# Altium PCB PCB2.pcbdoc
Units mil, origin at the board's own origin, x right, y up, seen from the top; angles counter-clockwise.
Board outline 3315 x 2785 mil, 2 copper layers (Top Layer, Bottom Layer), stack 62.206 mil thick; 34 components, 22 nets, 101 pads, 38 vias.
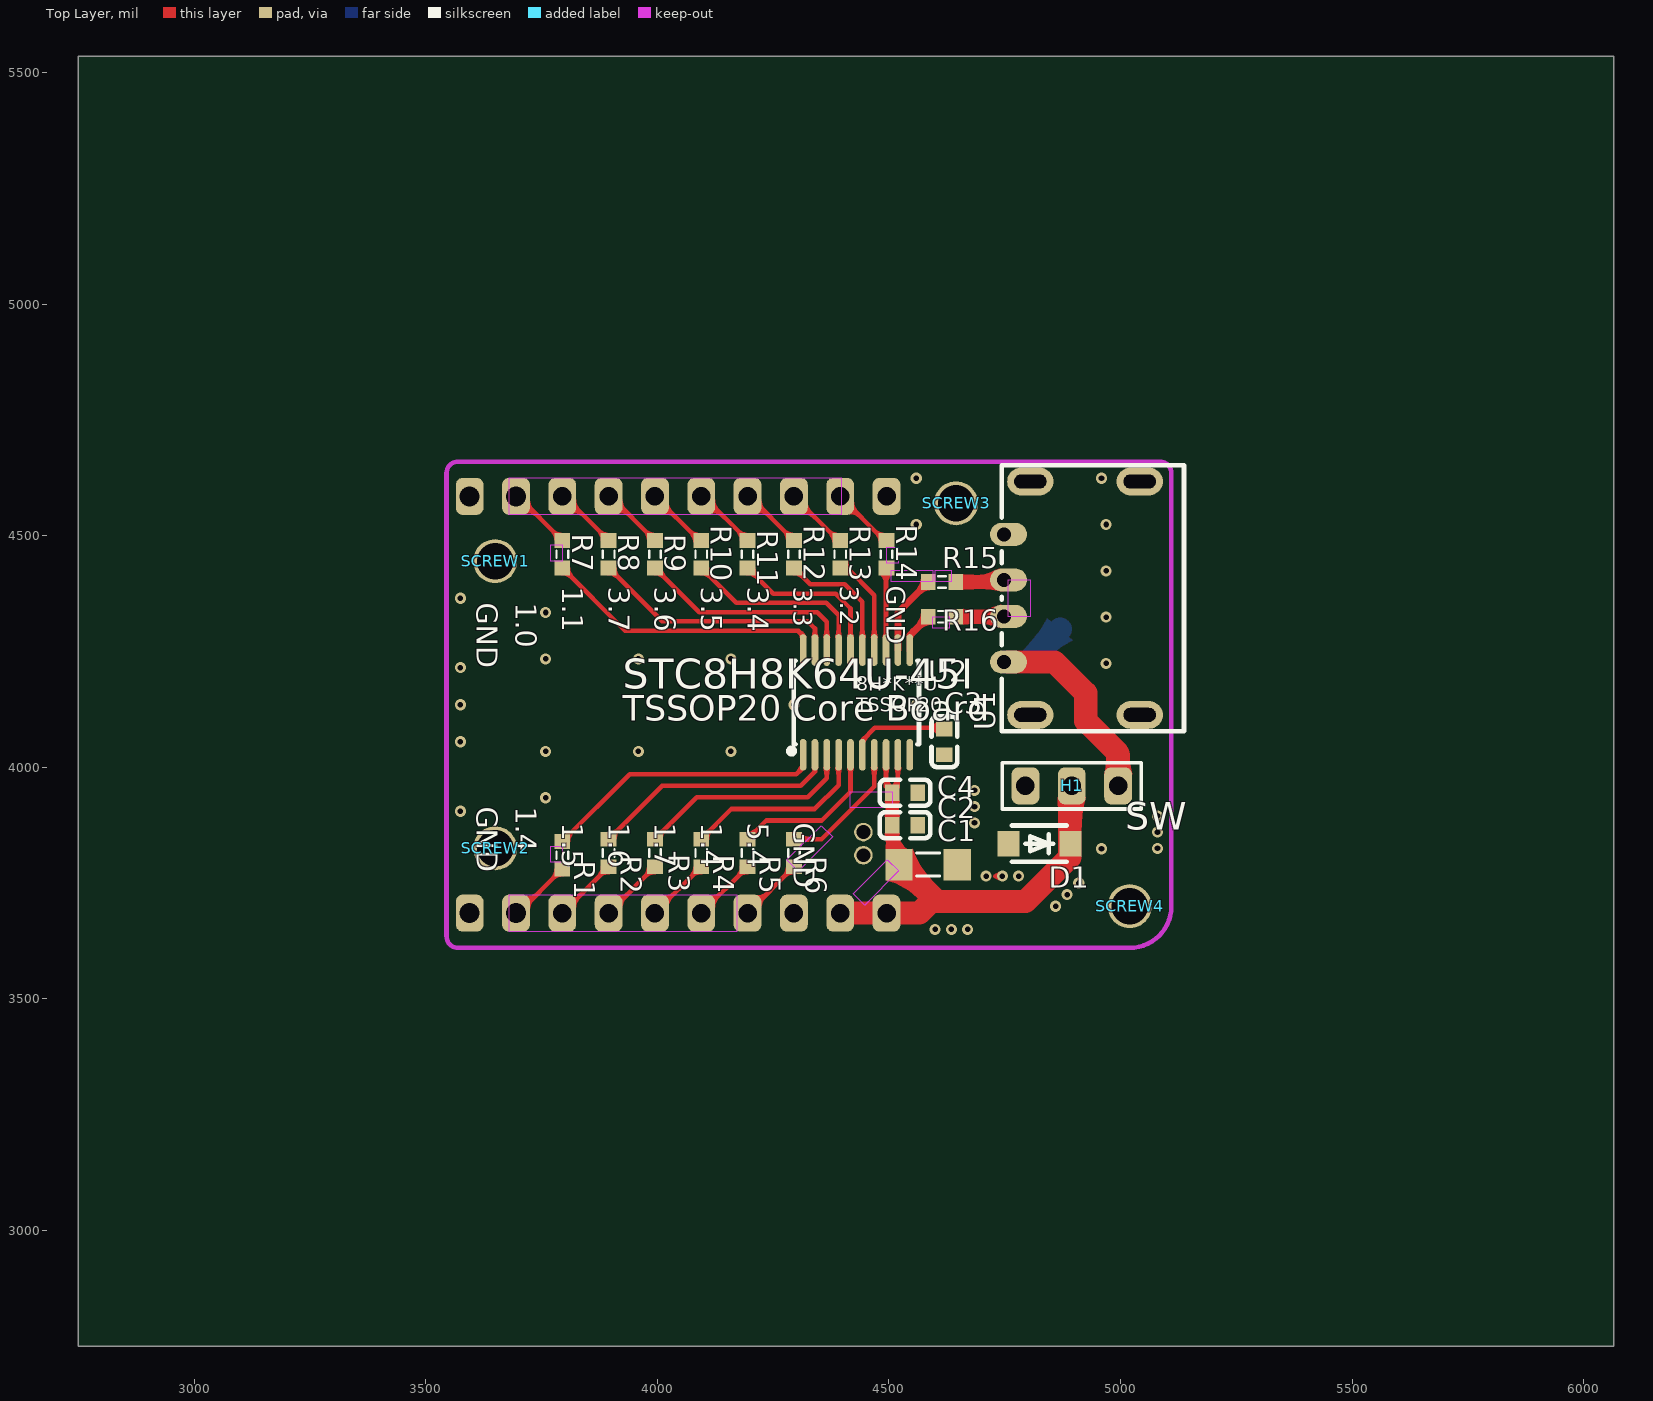
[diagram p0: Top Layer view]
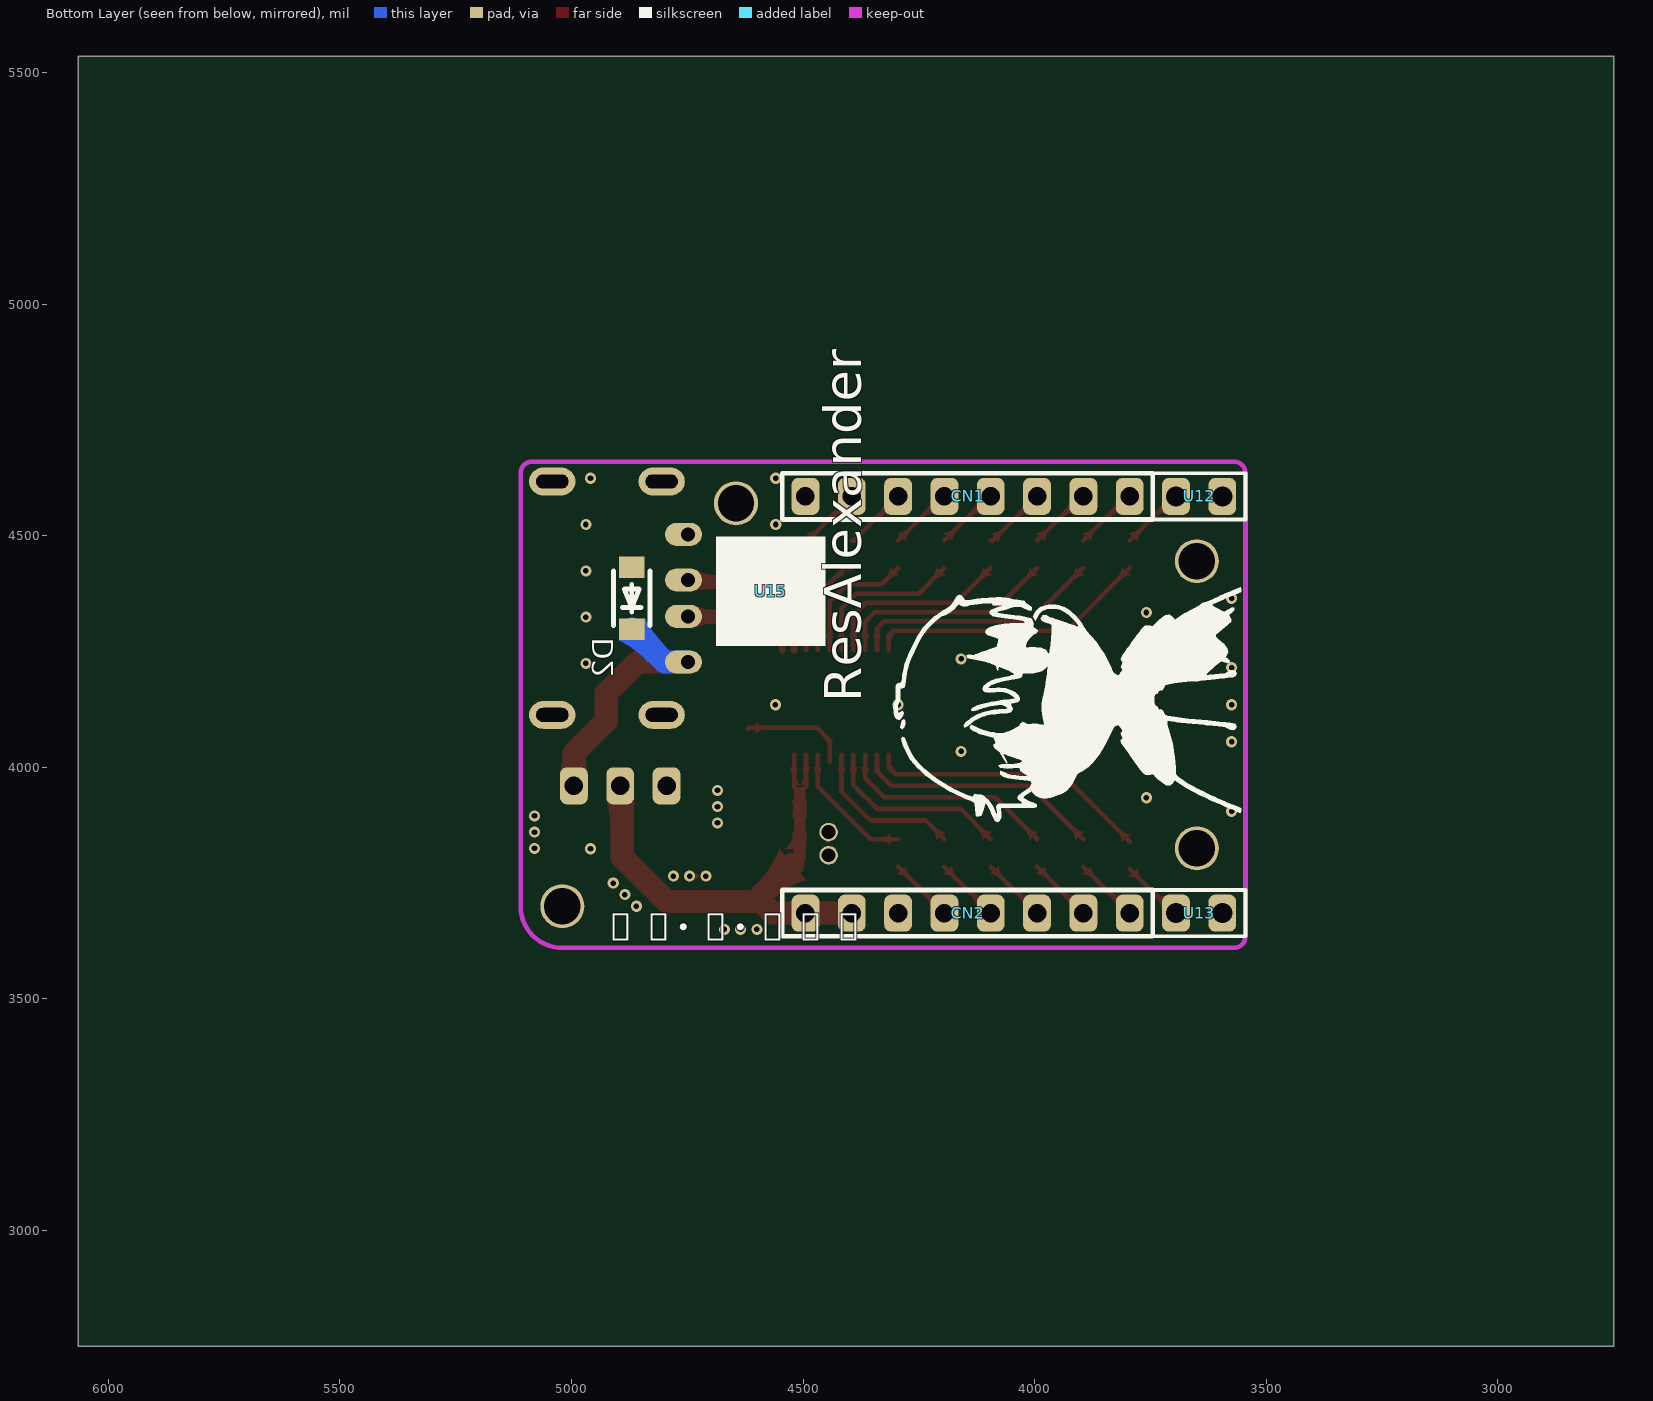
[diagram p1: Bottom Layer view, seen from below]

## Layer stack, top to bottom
Top Solder Mask Layer: solder mask 0.394, Dk 3.3
Top Layer: signal copper 1.379
Dielectric1: surface 59.449, FR4, Dk 4.5
Bottom Layer: signal copper 1.378
Bottom Solder Mask Layer: solder mask 0.394, Dk 3.3

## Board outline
6065,2750 2750,2750 2750,5535 6065,5535

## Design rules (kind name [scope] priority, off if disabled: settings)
BoardOutlineClearance copperThickness1oz [All] p0: genericclearance=10 ignorepadtopadclearanceinfootprint=FALSE except(0: Arc-SplitContinuation Track-SplitContinuation SMDPad-SplitContinuation THPad-SplitContinuation Via-SplitContinuation Fill-SplitContinuation Poly-SplitContinuation Region-SplitContinuation Text-SplitContinuation)
BoardOutlineClearance copperThickness2oz [All] p0: genericclearance=10 ignorepadtopadclearanceinfootprint=FALSE except(0: Arc-SplitContinuation Track-SplitContinuation SMDPad-SplitContinuation THPad-SplitContinuation Via-SplitContinuation Fill-SplitContinuation Poly-SplitContinuation Region-SplitContinuation Text-SplitContinuation)
BoardOutlineClearance otherClearance [All] p0: genericclearance=10 ignorepadtopadclearanceinfootprint=FALSE except(0: Arc-SplitContinuation Track-SplitContinuation SMDPad-SplitContinuation THPad-SplitContinuation Via-SplitContinuation Fill-SplitContinuation Poly-SplitContinuation Region-SplitContinuation Text-SplitContinuation)
Clearance copperThickness1oz [All] p1: gap=7 ignorepadtopadclearanceinfootprint=FALSE
Clearance copperThickness2oz [All] p1: gap=7 ignorepadtopadclearanceinfootprint=FALSE
Clearance otherClearance [All] p1: gap=7 ignorepadtopadclearanceinfootprint=FALSE
DiffPairsRouting differentialPair [All] p1: maxuncoupledlength=10 minlimit=6 maxlimit=Infinity mostfreqgap=6 toplayer_minwidth=5 toplayer_prefwidth=10 toplayer_maxwidth=100 bottomlayer_minwidth=5 bottomlayer_prefwidth=10 bottomlayer_maxwidth=100
PasteMaskExpansion pasteMaskExpansion [All] p1: expansion=0
PlaneConnect innerPlane [All] p1: planeconnectstyle=Relief reliefexpansion=20 reliefentries=4 reliefconductorwidth=10 reliefairgap=10
PolygonConnect copperRegion [All] p1: connectstyle=Direct reliefentries=4 reliefconductorwidth=10 polygonreliefangle="90 Angle" airgapwidth=10
RoutingVias viaSize [All] p1: viastyle="Through Hole" holewidth=12.0078 minholewidth=11.811 maxholewidth=248.0314 width=12.0078 minwidth=11.811 maxwidth=248.0314
SolderMaskExpansion solderMaskExpansion [All] p1: useseparateexpansions=TRUE expansion=2 expansionbottom=2
Width copperThickness1oz [All] p1: maxlimit=100 minlimit=5 preferedwidth=10
Width copperThickness2oz [All] p1: maxlimit=100 minlimit=8 preferedwidth=10

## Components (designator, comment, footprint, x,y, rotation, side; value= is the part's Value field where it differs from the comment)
C1 "" C1206 4585,3790 r180 top locked
C2 "" C0603 4535,3875 r180 top locked
C3 "" C0603 4620,4055 r270 top locked
C4 "" C0603 4535,3945 r180 top locked
CN1 "" HDR-TH_8P-P2.54-V-M-4 4145,4585 r0 bottom locked
CN2 "" HDR-TH_8P-P2.54-V-M-4 4145,3685 r0 bottom locked
D1 "" SOD-123FL_L2.8-W1.9-LS3.7-RD 4825,3835 r180 top locked
D2 "" SOD-123FL_L2.8-W1.9-LS3.7-RD 4870,4365 r90 bottom locked
H1 "" HDR-TH_3P-P2.54-V-M-1 4895,3960 r180 top locked
R1 "" R0603 3795,3810 r90 top locked
R2 "" R0603 3895,3815 r90 top locked
R3 "" R0603 3995,3815 r90 top locked
R4 "" R0603 4095,3815 r90 top locked
R5 "" R0603 4195,3815 r90 top locked
R6 "" R0603 4295,3815 r90 top locked
R7 "" R0603 3795,4460 r90 top locked
R8 "" R0603 3895,4460 r90 top locked
R9 "" R0603 3995,4460 r90 top locked
R10 "" R0603 4095,4460 r90 top locked
R11 "" R0603 4195,4460 r90 top locked
R12 "" R0603 4295,4460 r90 top locked
R13 "" R0603 4395,4460 r90 top locked
R14 "" R0603 4495,4460 r90 top locked
R15 "" R0603 4615,4400 r0 top locked
R16 "" R0603 4615,4325 r0 top locked
SCREW1 "" M2螺丝 3650,4445.05 r0 top locked
SCREW2 "" M2螺丝 3650,3825 r0 top locked
SCREW3 "" M2螺丝 4645,4570 r0 top locked
SCREW4 "" M2螺丝 5020,3700 r0 top locked
U1 "" USB-A-TH_XUBF-012-0404 4895,4365 r90 top locked
U2 "" TSSOP-20_L6.5-W4.4-P0.65-LS6.5-BL 4430,4140 r0 top locked
U12 "" HDR-TH_2P-P2.54-V-M-3 3645,4585 r0 bottom locked
U13 "" HDR-TH_2P-P2.54-V-M-3 3645,3685 r0 bottom locked
U15 "" JLC-QRCODE-6x6 4570,4380 r180 bottom locked

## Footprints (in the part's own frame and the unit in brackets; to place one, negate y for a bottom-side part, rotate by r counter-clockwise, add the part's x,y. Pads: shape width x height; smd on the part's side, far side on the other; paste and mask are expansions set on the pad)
C0603 [mm]
  rect 0.8x0.9 smd: 1(-0.7,0) 2(0.7,0)
  silkscreen extent -1.39,-0.71 1.39,0.71
C1206 [mm]
  rect 1.485x1.728 smd: 1(-1.593,0) 2(1.593,0)
  silkscreen extent -0.64,-0.64 0.64,0.64
HDR-TH_2P-P2.54-V-M-3 [mil]
  rrect50% 60x80 hole 43.31: 1(-50,0) 2(50,0)
  silkscreen extent -100,-50 100,50
HDR-TH_3P-P2.54-V-M-1 [mil]
  rrect50% 60x80 hole 40: 1(-100,0) 2(0,0) 3(100,0)
  silkscreen extent -150,-50 150,50
HDR-TH_8P-P2.54-V-M-4 [mil]
  rrect50% 60x80 hole 40: 1(-350,0) 2(-250,0) 3(-150,0) 4(-50,0) 5(50,0) 6(150,0) 7(250,0) 8(350,0)
  silkscreen extent -400,-50 400,50
JLC-QRCODE-6x6 [mil]
  silkscreen extent -118,-118 118,118
M2螺丝 [mil]
  round 95 hole 78.7: 1(0,0)
R0603 [mil]
  rect 31.75x34.02 smd: 1(-29.66,0) 2(29.66,0)
  silkscreen extent -8,-12 8,12
SOD-123FL_L2.8-W1.9-LS3.7-RD [mm]
  rect 1.2x1.4 smd: 1(-1.7,0) 2(1.7,0)
  silkscreen extent -1.5,-1 1.5,1
TSSOP-20_L6.5-W4.4-P0.65-LS6.5-BL [mil]
  oval 14.33x68.58 smd: 1(-115.16,-113.03) 2(-89.57,-113.03) 3(-63.98,-113.03) 4(-38.39,-113.03) 5(-12.79,-113.03) 6(12.8,-113.03) 7(38.39,-113.03) 8(63.98,-113.03) 9(89.57,-113.03) 10(115.16,-113.03) 11(115.16,113.03) 12(89.57,113.03) 13(63.98,113.03) 14(38.39,113.03) 15(12.8,113.03) 16(-12.79,113.03) 17(-38.39,113.03) 18(-63.98,113.03) 19(-89.57,113.03) 20(-115.16,113.03)
  silkscreen extent -146,-111 135,90
USB-A-TH_XUBF-012-0404 [mil]
  oval 50x80 hole 30 copper offset 0,-10: 1(-137.8,146.7) 4(137.8,146.7)
  oval 50x80 hole 30 copper offset 0.01,-10: 2(-39.37,146.7) 3(39.37,146.7)
  oval 60x100 hole 30 slot 70 at 90 deg: 5(-251.97,89.57) 6(251.97,89.57) 7(-251.97,-146.65) 8(251.97,-146.65)
  silkscreen extent -287,-242 287,151

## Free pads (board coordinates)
  round 40 hole 30: 1(4445,3810) 1(4445,3860)

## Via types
v1: diameter 24.02, hole 12.01, Top Layer to Bottom Layer, 38 vias

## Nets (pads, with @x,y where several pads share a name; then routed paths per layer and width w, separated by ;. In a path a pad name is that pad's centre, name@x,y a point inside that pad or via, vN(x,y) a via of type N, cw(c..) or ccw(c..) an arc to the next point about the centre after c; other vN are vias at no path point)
$1N2: D2.1 H1.1 U1.1 | length 574.5
  Top Layer w50: U1.1@4758.3,4227.2 4857.8,4227.2 4925,4160 4925,4100 4995,4030 H1.1
  Bottom Layer w50: U1.1 4799.13,4227.2 D2.1
$1N10: R15.1 U2.12 | length 174.2
  Top Layer w15: U2.12 4519.57,4334.23 R15.1
$1N11: R16.1 U2.11 | length 88.6
  Top Layer w15: U2.11 4545.16,4284.82 R16.1
$1N17: C3.1 U2.6 | length 235.3
  Top Layer w10: U2.6@4442.8,4011.97 4442.8,4057.8 4470,4085 4617.56,4085 C3.1
$1N19: R1.2 U2.1 | length 613.3
  Top Layer w10: R1.2 3940.34,3985 4300,3985 4314.84,3999.84 U2.1
$1N20: R2.2 U2.2 | length 542.3
  Top Layer w10: R2.2 4010.34,3960 4310,3960 4340.43,3990.43 U2.2
$1N21: R3.2 U2.3 | length 476.4
  Top Layer w10: R3.2 4085.34,3935 4325,3935 4366.02,3976.02 U2.3
$1N22: R4.2 U2.4 | length 410.4
  Top Layer w10: R4.2 4160.34,3910 4340,3910 4391.61,3961.61 U2.4
$1N23: R5.2 U2.5 | length 344.4
  Top Layer w10: R5.2 4235.34,3885 4355,3885 4417.21,3947.21 U2.5
$1N24: R6.2 U2.7 | length 289.1
  Top Layer w10: R6.2 4354.66,3844.66 4468.39,3958.39 U2.7
$1N25: R7.1 U2.20 | length 612.1
  Top Layer w10: R7.1 3930.34,4295 4305,4295 4314.84,4285.16 U2.20
$1N26: R8.1 U2.19 | length 546.1
  Top Layer w10: R8.1 4010.34,4315 4325,4315 4340.43,4299.57 U2.19
$1N27: R9.1 U2.18 | length 480.2
  Top Layer w10: R9.1 4090.34,4335 4345,4335 4366.02,4313.98 U2.18
$1N28: R10.1 U2.17 | length 414.2
  Top Layer w10: R10.1 4170.34,4355 4365,4355 4391.61,4328.39 U2.17
$1N29: R11.1 U2.16 | length 348.2
  Top Layer w10: R11.1 4250.34,4375 4385,4375 4417.21,4342.79 U2.16
$1N30: R12.1 U2.15 | length 282.3
  Top Layer w10: R12.1 4330.34,4395 4405,4395 4442.8,4357.2 U2.15
$1N31: R13.1 U2.14 | length 216.3
  Top Layer w10: R13.1 4409.66,4430.34 4468.39,4371.61 U2.14
$1N32: R14.1 U2.13 | length 177.7
  Top Layer w10: U2.13 4493.98,4429.32 R14.1
+5V: C1.2 C2.2 C4.2 CN2.7 CN2.8 D1.1 H1.2 U2.8 U2.9 | length 1153.3
  Top Layer w10: U2.8 4493.98,3958.46 C4.2 4519.57,3957.13 U2.9
  Top Layer w25: C4.2 C2.2 4507.44,3804.86 C1.2
  Top Layer w50: CN2.7 CN2.8 4565.71,3685 4590.71,3710 4605,3710 ; C1.2 4525,3790 4605,3710 ; H1.2 4890.75,3955.75 4890.75,3805.75 4795,3710 4605,3710
GND: C1.1 C2.1 C3.2 C4.1 CN1.8 CN2.6 D1.2 D2.2 H1.3 pad.1 SCREW1.1 SCREW2.1 SCREW3.1 SCREW4.1 U1.4 U1.5 U1.6 U1.7 U1.8 U2.10 U12.1 U13.1 | length 15
  Top Layer w10: 4730,3765 v1(4745,3765)
  other v1: 4600,3650 4635,3650 4670,3650 4860,3700 4885,3725 4910,3750 4710,3765 4780,3765 4959.1,3824.1 5080,3825 5080,3860 4685,3880 5080,3895 3575,3905 4685,3915 3759.1,3934.1 4685,3950 3759.1,4034.1 3959.1,4034.1 4159.1,4034.1 3575,4055 3575,4135 4295,4135 4560,4135 3575,4215 4969.1,4224.1 3759.1,4234.1 3959.1,4234.1 4159.1,4234.1 4969.1,4324.1 3759.1,4334.1 3575,4365 4969.1,4424.1 4559.1,4524.1 4969.1,4524.1 4559.1,4624.1 4959.1,4624.1
USB_D+: R15.2 U1.3 | length 105.5
  Top Layer w30: R15.2 4743.97,4400 U1.3
USB_D-: R16.2 U1.2 | length 103.9
  Top Layer w30: R16.2 4747.71,4325 U1.2
pads on no net: CN1.1 CN1.2 CN1.3 CN1.4 CN1.5 CN1.6 CN1.7 CN2.1 CN2.2 CN2.3 CN2.4 CN2.5 R1.1 R2.1 R3.1 R4.1 R5.1 R6.1 R7.2 R8.2 R9.2 R10.2 R11.2 R12.2 R13.2 R14.2 U12.2 U13.2
copper on no net: | length 1964.2
  Top Layer w10: 3695,3685 3699.66,3685 3795,3780.34 ; 3695,4585 3699.66,4585 3795,4489.66 ; 3795,3685 3895,3785 3895,3785.34 ; 3795,4585 3799.66,4585 3895,4489.66 ; 3895,3685 3995,3785 3995,3785.34 ; 3895,4585 3899.66,4585 3995,4489.66 ; 3995,3685 3995,3685.34 4095,3785.34 ; 3995,4585 4090.34,4489.66 4095,4489.66 ; 4095,3685 4095,3685.34 4195,3785.34 ; 4095,4585 4099.66,4585 4195,4489.66 ; 4195,3685 4295,3785 4295,3785.34 ; 4195,4585 4199.66,4585 4295,4489.66 ; 4295,4585 4390.34,4489.66 4395,4489.66 ; 4395,4585 4490.34,4489.66 4495,4489.66

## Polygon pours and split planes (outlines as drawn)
GND on Top Layer (solid, remove dead copper, pour order 0): 3000,5285 5460,5285 5460,3350 3000,3350
GND on Bottom Layer (solid, remove dead copper, pour order 2): 3355,4935 5815,4935 5815,3000 3355,3000

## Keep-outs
Top Layer:
  region: 3680,3725 4171.85,3725 4171.85,3645 3680,3645
  region: 3680,4625 4396.85,4625 4396.85,4545 3680,4545
  region: 4758.3,4404.38 4805,4404.38 4805,4325 4758.3,4325
  region: 4417.21,3947.21 4507.44,3947.21 4507.44,3912.46 4417.21,3912.46
  region: 4423.25,3726.87 4497.06,3800.67 4521.63,3776.1 4447.82,3702.3
  region: 4280.07,3800.38 4353.87,3874.19 4378.44,3849.62 4304.64,3775.81
  region: 3770,3830 3795,3830 3795,3795 3770,3795
  region: 3770,4480 3795,4480 3795,4445 3770,4445
  region: 4595,4299.8 4595,4324.8 4630,4324.8 4630,4299.8
  region: 4635,4425 4635,4400 4600,4400 4600,4425
  region: 4520.39,4440 4495.39,4440 4495.39,4475 4520.39,4475
  region: 4595,4425.2 4595,4400.2 4505,4400.2 4505,4425.2
Board Outline Layer:
  lines w10: 3545,3635 3545,4635 cw(c3570,4635) 3570,4660 5085,4660 cw(c5085,4635) 5110,4635 5110,3700 cw(c5020,3700) 5020,3610 3570,3610 cw(c3570,3635) 3545,3635

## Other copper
Top Layer:
  region net $1N32: 4498.98,4399.46 4488.98,4399.46 ccw(c4470.23,4399.46) 4481.48,4414.46 4506.48,4414.46 ccw(c4517.73,4399.46)
  region net $1N32: 4488.98,4295.16 4498.98,4295.16 4499.07,4292.91 4499.32,4290.71 4500.06,4286.54 4500.81,4282.93 4501.15,4280.16 4486.81,4280.16 4487.15,4282.93 4487.9,4286.54 4488.64,4290.71 4488.89,4292.91
  region net +5V: 4494.94,3861.52 4519.94,3861.52 ccw(c4566.81,3861.52) 4538.69,3824.02 4493.07,3824.02 ccw(c4118.5,3861.52)
  region net +5V: 4591.97,3758.39 4561.4,3718.25 ccw(c4461.81,3618.67) 4493.07,3755.98 4551.53,3824.02 ccw(c4709.91,3876.32)
  region net +5V: 4519.94,3819.78 4494.94,3819.78 ccw(c4276.84,3819.78) 4491.69,3857.28 4523.19,3857.28 ccw(c4738.04,3819.78)
  region net +5V: 4494.94,3930.22 4519.94,3930.22 ccw(c4738.04,3930.22) 4523.19,3892.72 4491.69,3892.72 ccw(c4276.84,3930.22)
  region net +5V: 4488.98,3977.72 4498.98,3977.72 ccw(c4517.73,3977.72) 4506.48,3962.72 4491.69,3962.72 ccw(c4448.85,3962.72)
  region net +5V: 4514.57,3977.72 4524.57,3977.72 ccw(c4605.28,3962.72) 4523.19,3962.72 4507.07,3962.72 ccw(c4495.82,3977.72)
  region net +5V: 4519.94,3889.78 4494.94,3889.78 ccw(c4276.84,3889.78) 4491.69,3927.28 4523.19,3927.28 ccw(c4738.04,3889.78)
  region net +5V: 4915.75,3860 4865.75,3860 ccw(c1107.91,3860) 4865,3935 4925,3935 ccw(c5224.38,3860)
  region net $1N2: 4970,4030 5020,4030 ccw(c5225,4030) 5025,3985 4965,3985 ccw(c4765,4030)
  region net USB_D+: 4705.54,4415 4705.54,4385 ccw(c4705.54,3879.76) 4660.54,4382.99 4660.54,4417.01 ccw(c4705.54,4920.24)
  region net $1N10: 4570.98,4375.04 4561.51,4386.78 ccw(c4529.69,4410.64) 4569.46,4410.64 4594.85,4382.99 ccw(c4594.85,4343.22)
  region net USB_D-: 4705.54,4340 4705.54,4310 ccw(c4705.54,3804.76) 4660.54,4307.99 4660.54,4342.01 ccw(c4705.54,4845.24)
  region net $1N11: 4570.98,4300.04 4561.51,4311.78 ccw(c4529.69,4335.64) 4569.46,4335.64 4594.85,4307.99 ccw(c4594.85,4268.22)
  region net $1N19: 4307.77,3985.7 4300.7,3992.77 4302.22,3994.42 4303.6,3996.15 4306.02,3999.63 4308.05,4002.7 4309.77,4004.91 4319.91,3994.78 4317.71,3993.05 4314.63,3991.03 4311.16,3988.61 4309.42,3987.22
  region net $1N20: 4345.43,3990.43 4335.43,3990.43 4335.34,3991.84 4335.09,3993.22 4334.35,3995.82 4333.6,3998.09 4333.26,3999.84 4347.6,3999.84 4347.26,3998.09 4346.51,3995.82 4345.77,3993.22 4345.52,3991.84
  region net $1N21: 4371.02,3984.84 4361.02,3984.84 4360.93,3987.09 4360.68,3989.29 4359.94,3993.46 4359.19,3997.07 4358.85,3999.84 4373.19,3999.84 4372.85,3997.07 4372.1,3993.46 4371.36,3989.29 4371.11,3987.09
  region net $1N22: 4396.61,3984.84 4386.61,3984.84 4386.52,3987.09 4386.27,3989.29 4385.53,3993.46 4384.78,3997.07 4384.44,3999.84 4398.78,3999.84 4398.44,3997.07 4397.69,3993.46 4396.95,3989.29 4396.7,3987.09
  region net $1N23: 4422.21,3984.84 4412.21,3984.84 4412.12,3987.09 4411.87,3989.29 4411.13,3993.46 4410.38,3997.07 4410.04,3999.84 4424.38,3999.84 4424.04,3997.07 4423.29,3993.46 4422.55,3989.29 4422.3,3987.09
  region net $1N17: 4444.44,4066.51 4458.67,4066.6 4455.52,4063.29 4452.73,4059.9 4451.6,4058.27 4450.73,4056.74 4450.17,4055.33 4449.97,4054.1 4435.63,4054.1 4435.84,4055.33 4436.41,4056.72 4437.3,4058.24 4438.44,4059.85 4441.27,4063.21
  region net $1N24: 4473.39,3984.84 4463.39,3984.84 4463.3,3987.09 4463.05,3989.29 4462.31,3993.46 4461.56,3997.07 4461.22,3999.84 4475.56,3999.84 4475.22,3997.07 4474.47,3993.46 4473.73,3989.29 4473.48,3987.09
  region net +5V: 4498.98,3984.84 4488.98,3984.84 4488.89,3987.09 4488.64,3989.29 4487.9,3993.46 4487.15,3997.07 4486.81,3999.84 4501.15,3999.84 4500.81,3997.07 4500.06,3993.46 4499.32,3989.29 4499.07,3987.09
  region net +5V: 4524.57,3984.84 4514.57,3984.84 4514.48,3987.09 4514.23,3989.29 4513.49,3993.46 4512.74,3997.07 4512.4,3999.84 4526.74,3999.84 4526.4,3997.07 4525.65,3993.46 4524.91,3989.29 4524.66,3987.09
  region net $1N25: 4301.46,4291.46 4313.85,4293.22 4316.92,4289.82 4319.52,4286.25 4320.54,4284.52 4321.33,4282.9 4321.83,4281.43 4322.01,4280.16 4307.67,4280.16 4307.53,4281.25 4307.14,4282.56 4305.73,4285.6 4303.74,4288.75
  region net $1N26: 4335.43,4295.16 4345.43,4295.16 4345.52,4292.91 4345.77,4290.71 4346.51,4286.54 4347.26,4282.93 4347.6,4280.16 4333.26,4280.16 4333.6,4282.93 4334.35,4286.54 4335.09,4290.71 4335.34,4292.91
  region net $1N27: 4361.02,4295.16 4371.02,4295.16 4371.11,4292.91 4371.36,4290.71 4372.1,4286.54 4372.85,4282.93 4373.19,4280.16 4358.85,4280.16 4359.19,4282.93 4359.94,4286.54 4360.68,4290.71 4360.93,4292.91
  region net $1N28: 4386.61,4295.16 4396.61,4295.16 4396.7,4292.91 4396.95,4290.71 4397.69,4286.54 4398.44,4282.93 4398.78,4280.16 4384.44,4280.16 4384.78,4282.93 4385.53,4286.54 4386.27,4290.71 4386.52,4292.91
  region net $1N29: 4412.21,4295.16 4422.21,4295.16 4422.3,4292.91 4422.55,4290.71 4423.29,4286.54 4424.04,4282.93 4424.38,4280.16 4410.04,4280.16 4410.38,4282.93 4411.13,4286.54 4411.87,4290.71 4412.12,4292.91
  region net $1N30: 4437.8,4295.16 4447.8,4295.16 4447.89,4292.91 4448.14,4290.71 4448.88,4286.54 4449.63,4282.93 4449.97,4280.16 4435.63,4280.16 4435.97,4282.93 4436.72,4286.54 4437.46,4290.71 4437.71,4292.91
  region net $1N31: 4463.39,4295.16 4473.39,4295.16 4473.48,4292.91 4473.73,4290.71 4474.47,4286.54 4475.22,4282.93 4475.56,4280.16 4461.22,4280.16 4461.56,4282.93 4462.31,4286.54 4463.05,4290.71 4463.3,4292.91
  region net $1N11: 4549.85,4300.12 4567.62,4296.68 4565.14,4294.32 4562.55,4292.04 4557.59,4287.72 4555.49,4285.68 4553.82,4283.74 4552.72,4281.9 4552.43,4281.01 4552.33,4280.16 4537.99,4280.16 4538.24,4282.09 4538.95,4284.34 4540.07,4286.83 4541.54,4289.49 4543.3,4292.23 4545.31,4294.97 4547.52,4297.62
  region net USB_D-: 4698.94,4310 4697.66,4340 4701.04,4340.12 4704.39,4340.45 4707.71,4340.96 4710.99,4341.63 4717.38,4343.3 4723.45,4345.23 4734.26,4348.87 4738.82,4350.1 4740.83,4350.47 4742.66,4350.63 4743.94,4300.64 4742.11,4300.71 4740.1,4300.98 4735.56,4302.01 4724.74,4305.23 4718.66,4306.98 4712.27,4308.51 4708.98,4309.12 4705.66,4309.59 4702.31,4309.89
  region net USB_D+: 4702.68,4385 4693.93,4415 4697.29,4415.14 4700.65,4415.53 4703.97,4416.15 4707.25,4416.95 4713.63,4418.99 4719.7,4421.38 4730.51,4426.11 4735.07,4427.91 4737.09,4428.56 4738.93,4428.99 4747.68,4379.76 4745.9,4379.56 4743.92,4379.53 4739.41,4379.91 4734.26,4380.72 4728.58,4381.79 4722.47,4382.92 4716.05,4383.96 4709.41,4384.71
  region net $1N17: 4587.28,4080 4587.28,4090 ccw(c4587.28,4108.75) 4602.28,4097.5 4602.28,4072.5 ccw(c4587.28,4061.25)
  region net $1N19: 3809.11,3860.84 3817.31,3854.9 ccw(c3838.52,3838.99) 3812.01,3838.99 3793.2,3855.54 ccw(c3793.2,3882.05)
  region: 3780.89,3759.16 3772.69,3765.1 ccw(c3751.48,3781.01) 3777.99,3781.01 3796.8,3764.46 ccw(c3796.8,3737.95)
  region net $1N20: 3909.11,3865.84 3917.31,3859.9 ccw(c3938.52,3843.99) 3912.01,3843.99 3893.2,3860.54 ccw(c3893.2,3887.05)
  region: 3881.23,3764.16 3872.69,3769.76 ccw(c3851.48,3785.67) 3877.99,3785.67 3897.14,3769.46 ccw(c3897.14,3742.95)
  region net $1N21: 4009.11,3865.84 4017.31,3859.9 ccw(c4038.52,3843.99) 4012.01,3843.99 3993.2,3860.54 ccw(c3993.2,3887.05)
  region: 3981.23,3764.16 3972.69,3769.76 ccw(c3951.48,3785.67) 3977.99,3785.67 3997.14,3769.46 ccw(c3997.14,3742.95)
  region net $1N22: 4109.11,3865.84 4117.31,3859.9 ccw(c4138.52,3843.99) 4112.01,3843.99 4093.2,3860.54 ccw(c4093.2,3887.05)
  region: 4080.89,3764.16 4072.69,3770.1 ccw(c4051.48,3786.01) 4077.99,3786.01 4096.8,3769.46 ccw(c4096.8,3742.95)
  region net $1N23: 4209.11,3865.84 4217.31,3859.9 ccw(c4238.52,3843.99) 4212.01,3843.99 4193.2,3860.54 ccw(c4193.2,3887.05)
  region: 4180.89,3764.16 4172.69,3770.1 ccw(c4151.48,3786.01) 4177.99,3786.01 4196.8,3769.46 ccw(c4196.8,3742.95)
  region net $1N24: 4327.01,3849.66 4327.01,3839.66 ccw(c4327.01,3820.91) 4312.01,3832.16 4312.01,3857.16 ccw(c4327.01,3868.41)
  region: 4281.23,3764.16 4272.69,3769.76 ccw(c4251.48,3785.67) 4277.99,3785.67 4297.14,3769.46 ccw(c4297.14,3742.95)
  region: 3772.69,4504.9 3780.89,4510.84 ccw(c3796.8,4532.05) 3796.8,4505.54 3777.99,4488.99 ccw(c3751.48,4488.99)
  region net $1N25: 3817.31,4415.1 3809.11,4409.16 ccw(c3793.2,4387.95) 3793.2,4414.46 3812.01,4431.01 ccw(c3838.52,4431.01)
  region: 3872.69,4504.9 3880.89,4510.84 ccw(c3896.8,4532.05) 3896.8,4505.54 3877.99,4488.99 ccw(c3851.48,4488.99)
  region net $1N26: 3917.31,4415.1 3909.11,4409.16 ccw(c3893.2,4387.95) 3893.2,4414.46 3912.01,4431.01 ccw(c3938.52,4431.01)
  region: 3972.69,4504.9 3980.89,4510.84 ccw(c3996.8,4532.05) 3996.8,4505.54 3977.99,4488.99 ccw(c3951.48,4488.99)
  region net $1N27: 4017.31,4415.1 4009.11,4409.16 ccw(c3993.2,4387.95) 3993.2,4414.46 4012.01,4431.01 ccw(c4038.52,4431.01)
  region: 4072.69,4500.24 4076.23,4510.84 ccw(c4092.14,4532.05) 4092.14,4505.54 4077.99,4484.33 ccw(c4051.48,4484.33)
  region net $1N28: 4117.31,4415.1 4109.11,4409.16 ccw(c4093.2,4387.95) 4093.2,4414.46 4112.01,4431.01 ccw(c4138.52,4431.01)
  region: 4172.69,4504.9 4180.89,4510.84 ccw(c4196.8,4532.05) 4196.8,4505.54 4177.99,4488.99 ccw(c4151.48,4488.99)
  region net $1N29: 4217.31,4415.1 4209.11,4409.16 ccw(c4193.2,4387.95) 4193.2,4414.46 4212.01,4431.01 ccw(c4238.52,4431.01)
  region: 4272.69,4504.9 4280.89,4510.84 ccw(c4296.8,4532.05) 4296.8,4505.54 4277.99,4488.99 ccw(c4251.48,4488.99)
  region net $1N30: 4317.31,4415.1 4309.11,4409.16 ccw(c4293.2,4387.95) 4293.2,4414.46 4312.01,4431.01 ccw(c4338.52,4431.01)
  region: 4372.69,4500.24 4376.23,4510.84 ccw(c4392.14,4532.05) 4392.14,4505.54 4377.99,4484.33 ccw(c4351.48,4484.33)
  region net $1N31: 4417.31,4429.76 4425.84,4407.09 ccw(c4406.8,4388.05) 4412.01,4414.46 4412.01,4445.67 ccw(c4438.52,4445.67)
  region: 4472.69,4500.24 4476.23,4510.84 ccw(c4492.14,4532.05) 4492.14,4505.54 4477.99,4484.33 ccw(c4451.48,4484.33)
  region: 4430.3,4556.77 4431.9,4541.03 ccw(c4418.85,4527.98) 4415.84,4546.19 4425,4572.68 ccw(c4451.52,4572.68)
  region: 4330.3,4556.77 4331.9,4541.03 ccw(c4318.85,4527.98) 4315.84,4546.19 4325,4572.68 ccw(c4351.52,4572.68)
  region: 4230.3,4561.43 4234.88,4542.71 ccw(c4221.84,4529.68) 4218.81,4547.86 4225,4577.34 ccw(c4251.52,4577.34)
  region: 4130.3,4561.43 4134.88,4542.71 ccw(c4121.84,4529.68) 4118.81,4547.86 4125,4577.34 ccw(c4151.52,4577.34)
  region: 4030.3,4556.77 4031.9,4541.03 ccw(c4018.85,4527.98) 4015.84,4546.19 4025,4572.68 ccw(c4051.52,4572.68)
  region: 3930.3,4561.43 3934.88,4542.71 ccw(c3921.84,4529.68) 3918.81,4547.86 3925,4577.34 ccw(c3951.52,4577.34)
  region: 3830.3,4561.43 3834.88,4542.71 ccw(c3821.84,4529.68) 3818.81,4547.86 3825,4577.34 ccw(c3851.52,4577.34)
  region: 4231.9,3728.97 4230.3,3713.23 ccw(c4251.52,3697.32) 4225,3697.32 4215.84,3723.81 ccw(c4218.85,3742.02)
  region: 4131.66,3729.08 4130.3,3713.57 ccw(c4151.52,3697.66) 4125,3697.66 4115.62,3723.91 ccw(c4118.6,3742.14)
  region: 4031.66,3729.08 4030.3,3713.57 ccw(c4051.52,3697.66) 4025,3697.66 4015.62,3723.91 ccw(c4018.6,3742.14)
  region: 3931.9,3728.97 3930.3,3713.23 ccw(c3951.52,3697.32) 3925,3697.32 3915.84,3723.81 ccw(c3918.85,3742.02)
  region: 3831.9,3728.97 3830.3,3713.23 ccw(c3851.52,3697.32) 3825,3697.32 3815.84,3723.81 ccw(c3818.85,3742.02)
  region: 3730.3,4561.43 3734.88,4542.71 ccw(c3721.84,4529.68) 3718.81,4547.86 3725,4577.34 ccw(c3751.52,4577.34)
  region: 3734.88,3727.29 3730.3,3708.57 ccw(c3751.52,3692.66) 3725,3692.66 3718.81,3722.14 ccw(c3721.84,3740.32)
  region net GND: 4730,3760 4730,3770 4731.31,3770.34 4733.15,3771.25 4735.17,3772.53 4737.06,3774.01 4737.06,3755.99 4735.17,3757.47 4733.15,3758.75 4731.31,3759.66
Bottom Layer:
  region net $1N2: 4836.61,4229.33 4797.32,4260.75 ccw(c4615.65,4442.42) 4842.44,4321.69 4897.56,4274.45 ccw(c5018.29,4047.66)

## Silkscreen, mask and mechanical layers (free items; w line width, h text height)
Top Silkscreen Layer:
  text "3.2" at 4395,4391.64 h40 r270
  text "GND" at 4495,4391.64 h40 r270
  text "1.1" at 3795,4390 h45 r270
  text "3.7" at 3895,4390 h45 r270
  text "3.6" at 3995,4390 h45 r270
  text "3.5" at 4095,4390 h45 r270
  text "3.4" at 4195,4390 h45 r270
  text "3.3" at 4295,4390 h40 r270
  text "GND" at 3610,4355 h45 r270
  text "1.0" at 3695,4355 h45 r270
  text "STC8H8K64U-45I" at 3925,4170 h65
  text "8H*K**U" at 4430,4165 h30
  text "TSSOP20" at 4430,4120 h30
  text "TSSOP20 Core Board" at 3925,4100 h55
  text "GND" at 3610,3915 h45 r270
  text "1.4" at 3695,3915 h45 r270
  text "1.5" at 3795,3880 h45 r270
  text "1.6" at 3895,3880 h45 r270
  text "1.7" at 3995,3880 h45 r270
  text "1.4" at 4095,3880 h45 r270
  text "5.4" at 4195,3880 h45 r270
  text "GND" at 4295,3880 h45 r270
  text "SW" at 5010,3865 h60
Bottom Silkscreen Layer:
  drawing of 7 lines, arcs and shapes, not listed
  text "ResAlexander" at 4375,4140 h80 r270
  text "⎧ˊ･ω･ˋ⎫/" at 4935,3625 h60
Document Layer:
  lines w10: 4070,4036.02 4070,4225
  text "USB-A" at 5295,4535 h120 r270

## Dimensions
5172.6,4076.54 to 5172.6,4653.46 on Document Layer
3795,4680 to 3895,4680 on Document Layer
5110,4860 to 3545,4860 on Document Layer
3330,4660 to 3330,3610 on Document Layer
3475,4585 to 3475,3685 on Document Layer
